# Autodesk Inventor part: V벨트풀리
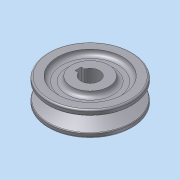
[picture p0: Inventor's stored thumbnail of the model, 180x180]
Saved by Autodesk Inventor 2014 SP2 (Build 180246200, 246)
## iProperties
Created: 2015-03
Part Number: V벨트풀리
Material: 강
Document SubType Name: Modeling
Designer: KYOUNG IL JANG
Density: 1 g/cm^3
Appearance: 강철
CustomPartVersion: 1
Author: KYOUNG IL JANG
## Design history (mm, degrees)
sketch "주 스케치"
  geometry: L1 (0, 16)-(27, 16); L2 (27, 16)-(27, 12.861); L3 (27, 12.861)-(16, 9.498); L4 (16, 9.498)-(16, 6.502); L5 (16, 6.502)-(27, 3.139); L6 (27, 3.139)-(27, 0); L7 (27, 0)-(0, 0); L8 (25, 12.25)-(25, 3.75); L9 (16, 8)-(25, 8); L10 (27, 12.861)-(27, 3.139); L11 (0, -3)-(0, 18) reference; L12 (0, 0)-(0, 16)
  constraints: 22 end point, 5 perpendicular, 2 collinear, 2 midpoint, 2 point on line, 1 parallel
  dimensions: "d0" = 8.5 distance of L8.start L8.end (= da_Bw); "d1" = 34 deg angle of L3 L5 (= da_Alfa); "d2" = 2 distance between parallel lines of L2 L8 (= da_c); "d6" = 16 distance between parallel lines of L7 L1 (computed from d5, da_ng, da_Sg); "d21" = 50 diameter of L8 L11 (= da_Dw); "d25" = 11 distance between parallel lines of L4 L10 (= da_Hd); "d27" = 8 distance between parallel lines of L7 L9 (= da_Se)
node "벨트 평면"
revolve "본체" stored, may be unused: angle "d7" = 90 deg
revolve "그루브" stored, may be unused: angle "d15" = 90 deg
feature "허브 키홈"
fillet "모깎기3" dims "d28" = 0.5, "d29" = 1, "d30" = 1
sketch "스케치2"
  geometry: C1 r 12 at (0, 0); C2 r 21 at (0, 0); 1 further point
  constraints: 2 centre point, 2 coincident
  dimensions: "d31" = 24 diameter of C1; "d32" = 42 diameter of C2
extrude "돌출1" cut sketch "스케치2" distance "d33" = 3; taper "d34" = 0 deg
fillet "모깎기4" dims "d35" = 3
node "작업 평면2"
body "Solid1"
pattern_linear "그루브 패턴" dims "d18" = 12 (= da_Sg)
mirror "대칭1"
other parameters: "d5" = 8 (= da_Se), "da_Bw" = 8.5 [user parameter; used in 1 equation term], "da_Alfa" = 34 deg [user parameter; used in 1 equation term], "da_c" = 2 [user parameter; used in 1 equation term], "da_Dw" = 50 [user parameter; used in 1 equation term], "da_Hd" = 11 [user parameter; used in 1 equation term], "da_Se" = 8 [user parameter; used in 2 equation terms], "da_Sg" = 12 [user parameter; used in 2 equation terms], "da_r1" = 0 [user parameter], "da_r2" = 0 [user parameter], "d24" = 0, "d26" = 0
